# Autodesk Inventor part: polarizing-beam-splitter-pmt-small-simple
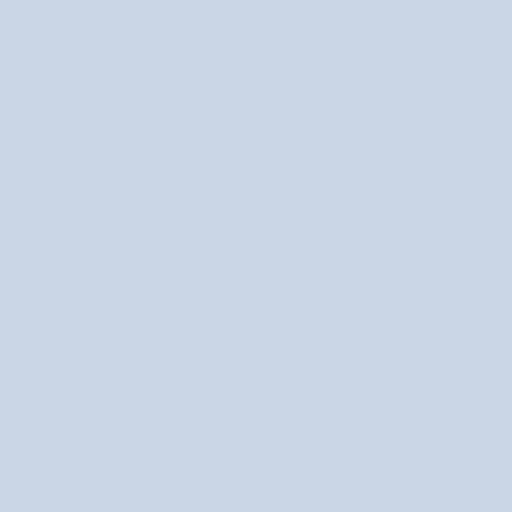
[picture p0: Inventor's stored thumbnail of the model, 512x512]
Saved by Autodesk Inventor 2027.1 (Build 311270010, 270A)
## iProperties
Created: 2026-08
Part Number: polarizing-beam-splitter-pmt-small-simple
Material: Generic
Document SubType Name: Modeling
Designer: dunge
Density: 1 g/cm^3
Appearance: Default
Author: dunge
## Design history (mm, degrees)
sketch "Sketch1"
  geometry: L1 (-7.938, 7.937)-(7.937, 7.937); L2 (7.937, 7.937)-(7.938, -7.938); L3 (7.938, -7.938)-(-7.938, -7.937); L4 (-7.938, -7.937)-(-7.938, 7.937); L5 (-7.938, 7.937)-(7.938, -7.938); L6 (7.937, 7.937)-(-7.938, -7.937); L7 (-6.667, -7.302)-(7.302, 6.667); L8 (7.302, 6.667)-(6.667, 7.302); L9 (6.667, 7.302)-(-7.302, -6.667); L10 (-7.302, -6.667)-(-6.667, -7.302); L11 (-6.667, -7.302)-(6.667, 7.302); L12 (7.302, 6.667)-(-7.302, -6.667); 1 further point
  constraints: 24 end point, 5 parallel, 4 midpoint, 3 perpendicular, 1 horizontal
  dimensions: "d0" = 15.875 distance of L2.end L3.end; "d1" = 0.635 horizontal distance of L7.end L8.end; "d2" = 0.635 distance from line of L1 L8.end
extrude "Extrusion1" new body sketch "Sketch1" stored distance "d3" = 15.875; taper "d4" = 0 deg
body "Solid1"
node "Finishes"
node "Finish1" dims "Finish1_Area" = 62.72709
node "Finish2" dims "Finish2_Area" = 213.23932
